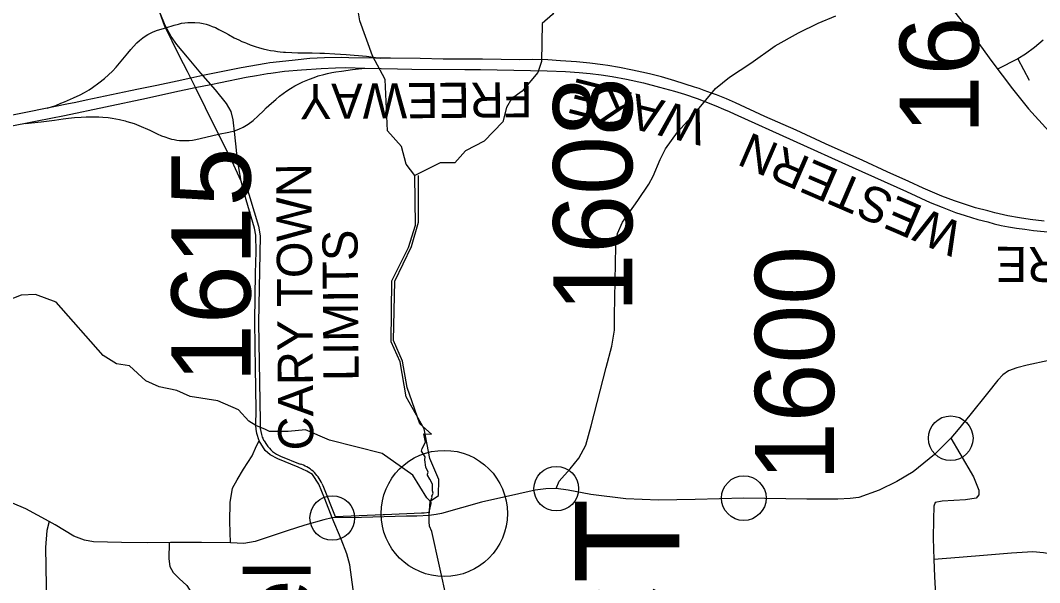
# Model space of a CAD drawing. Extents: x 2026893 to 2039781, y 729195 to 739590.
# Drawn here: x 2027257 to 2027941, y 735368 to 735746 of the extents above; entities that cross this region are included whole.
import ezdxf

# ---------------------------------------------------------------- set-up
doc = ezdxf.new("R2010")
doc.units = 0
doc.layers.add('Default', color=7, linetype='Continuous')
doc.layers.add('Old_Level_62', color=7, linetype='Continuous')

msp = doc.modelspace()

# ---------------------------------------------------------------- linework, layer by layer
at = {"layer": 'Default'}
for p, q in [((2027524.98, 735474.28), (2027516.61, 735498.7)), ((2027532.86, 735467.41), (2027524.98, 735474.28)), ((2027528.76, 735461.95), (2027527.62, 735467.5)), ((2027527.62, 735467.5), (2027532.86, 735467.41)), ((2027420.41, 735462.82), (2027422, 735460.32)), ((2027526.56, 735457.76), (2027528.76, 735461.95)), ((2027431.36, 735452.64), (2027444.56, 735447.3)), ((2027526.21, 735455.95), (2027526.56, 735457.76)), ((2027528.6, 735452.03), (2027526.21, 735455.95)), ((2027528.3, 735450.01), (2027528.6, 735452.03)), ((2027529.13, 735445.14), (2027528.3, 735450.01)), ((2027530.64, 735441.82), (2027529.13, 735445.14)), ((2027530.17, 735440.43), (2027530.64, 735441.82)), ((2027530.17, 735439.86), (2027530.17, 735440.43)), ((2027531.8, 735437.05), (2027530.17, 735439.86)), ((2027459.24, 735434.17), (2027459.85, 735432.79)), ((2027459.85, 735432.79), (2027468.11, 735412.09)), ((2027533.42, 735433.67), (2027531.8, 735437.05)), ((2027533.57, 735429.32), (2027533.42, 735433.67)), ((2027532.34, 735422.76), (2027533.28, 735425.07)), ((2027533.12, 735425.73), (2027533.99, 735427.6)), ((2027533.28, 735425.07), (2027533.12, 735425.73)), ((2027533.99, 735427.6), (2027533.57, 735429.32)), ((2027531.29, 735414.83), (2027532.53, 735420.69)), ((2027532.53, 735420.69), (2027532.34, 735422.76)), ((2027468.11, 735412.09), (2027500.45, 735413.32)), ((2027501.26, 735413.35), (2027526.17, 735414.47)), ((2027527.91, 735414.57), (2027531.29, 735414.83))]:
    msp.add_line(p, q, dxfattribs=at)
for points in [[(2027407.12, 735638.38), (2027416.67, 735607.09), (2027417.73, 735600.72), (2027416.67, 735542.12), (2027417.65, 735476.15)], [(2027516.61, 735498.7), (2027513.35, 735516.52), (2027507.26, 735530.38), (2027508.28, 735570.26), (2027519.44, 735593.58), (2027524.17, 735609.8), (2027524.17, 735641.23)]]:
    msp.add_lwpolyline(points, dxfattribs=at)
for centre, radius, start, end in [((2030089.05, 735530.09), 2671.94, 181.15687, 181.22222), ((2027441.76, 735473.6), 24.05, 181.20318, 200.27313), ((2027436.5, 735472.29), 18.67, 202.09732, 210.4951), ((2027439.63, 735472.25), 21.28, 214.09886, 247.1469), ((2027437.47, 735424.6), 23.78, 48.43914, 72.66828), ((2027437.47, 735424.6), 23.78, 23.72361, 48.4166), ((2027495.98, 735531.26), 118.03, 272.16812, 272.56587), ((2027523.57, 735472.53), 58.12, 272.56587, 274.28769)]:
    msp.add_arc(centre, radius, start, end, dxfattribs=at)
at = {"layer": 'Old_Level_62'}
for p, q in [((2027353.71, 735741.43), (2027350.15, 735751.52)), ((2027926.64, 735719.59), (2027913.12, 735712.74)), ((2027926.64, 735719.59), (2027934.3, 735705.36)), ((2027379.25, 735708.42), (2027371.14, 735706.64)), ((2027374.11, 735700.35), (2027384.55, 735702.46)), ((2027414.9, 735473.27), (2027414.9, 735473.27)), ((2027414.9, 735473.27), (2027414.9, 735473.27)), ((2027531.24, 735412.73), (2027531.24, 735412.73)), ((2027531.24, 735412.73), (2027531.24, 735412.73))]:
    msp.add_line(p, q, dxfattribs=at)
for points in [[(2027521.67, 735641.36), (2027515.72, 735648.85), (2027512.62, 735660.86), (2027503.18, 735671.36), (2027501.72, 735705.85), (2027493.19, 735721.81), (2027484.61, 735745.33), (2027482.69, 735757.33), (2027476.2, 735767.3), (2027477.64, 735779.83), (2027475.06, 735798.31), (2027471.59, 735801.79), (2027466.1, 735802.82), (2027461.06, 735806.78), (2027442.15, 735844.76), (2027431.63, 735859.75), (2027427.47, 735870.4)], [(2027625.65, 735787.88), (2027623.58, 735773.41), (2027618.1, 735755.89), (2027614.04, 735749.42), (2027607.22, 735743.42), (2027606.7, 735717.91), (2027604.18, 735710.42), (2027593.69, 735697.88), (2027586.7, 735692.9), (2027583.23, 735686.89), (2027580.67, 735677.42), (2027568.2, 735664.39), (2027555.66, 735657.86), (2027548.61, 735649.87), (2027538.77, 735649.87), (2027521.67, 735641.36)], [(2027869.52, 735781.98), (2027871.69, 735772.47), (2027872.9, 735768.1), (2027876.18, 735762.11), (2027884.25, 735751.35), (2027895.8, 735736.41), (2027909.27, 735717.87), (2027923.14, 735699.41), (2027933.81, 735686.04), (2027947.48, 735671.05), (2027962.36, 735656.86), (2027977.92, 735642.45), (2027988.16, 735632.6), (2027991.44, 735627.77), (2027993.37, 735621.31), (2027994.44, 735615.03), (2027994.73, 735610.2), (2027994.34, 735605.47), (2027993.23, 735595.53), (2027990.33, 735576.05), (2027985.79, 735545.25), (2027983.71, 735530.05)], [(2027414.9, 735473.27), (2027415.08, 735483.62), (2027414.54, 735512.2), (2027414.35, 735526.1), (2027414.06, 735543.5), (2027414.64, 735575.65), (2027415.12, 735590.04), (2027414.93, 735601.17), (2027413.92, 735605.94), (2027408.26, 735624.96), (2027404.88, 735637.51), (2027403.43, 735646.49), (2027402.36, 735653.66), (2027401.82, 735658.24), (2027400.83, 735668.87), (2027399.67, 735678.76), (2027398.22, 735684.36), (2027395.03, 735689.67), (2027387.78, 735698.75), (2027377.83, 735709.95), (2027369.04, 735720.88), (2027361.79, 735729.23), (2027357.93, 735734.73), (2027353.97, 735742.17), (2027350.59, 735750.47)], [(2027616.66, 735430.74), (2027618.69, 735435.76), (2027626.03, 735444.07), (2027631.73, 735451.21), (2027636.46, 735459.9), (2027640.13, 735473.03), (2027650.28, 735512.18), (2027654.05, 735526.47), (2027655.69, 735537.28), (2027655.69, 735547.13), (2027656.36, 735582.08), (2027656.75, 735593.85), (2027657.72, 735602.35), (2027661.19, 735609.88), (2027671.44, 735624.56), (2027678.88, 735635.42), (2027681.87, 735640.82), (2027686.41, 735652.12), (2027689.99, 735659.17), (2027698.1, 735670.46), (2027711.48, 735685.11), (2027723.7, 735699.84), (2027733.08, 735707.27), (2027747.37, 735716.71), (2027763.75, 735728.39), (2027779.35, 735737.2), (2027792.59, 735743.57), (2027804.38, 735748.5)], [(2027274.58, 735686.5), (2027280.56, 735688.4), (2027283.95, 735689.79), (2027286.26, 735690.82), (2027292.27, 735693.4), (2027296.74, 735695.51), (2027299.7, 735697.09), (2027302.79, 735698.87), (2027305.1, 735700.38), (2027309.4, 735703.51), (2027313.11, 735706.39), (2027318.6, 735711.44), (2027320.98, 735714.05), (2027328.86, 735723.5), (2027330.76, 735725.89), (2027332.59, 735728.06), (2027334.9, 735730.43), (2027336.68, 735732.1), (2027338.83, 735733.82), (2027340.6, 735735), (2027342.38, 735736.13), (2027344.04, 735736.94), (2027345.87, 735737.8), (2027348.67, 735738.93), (2027354.31, 735740.42)], [(2027371.14, 735706.68), (2027368.94, 735711.12), (2027363.67, 735721.53), (2027358.66, 735731.56), (2027353.71, 735741.43)], [(2027354.31, 735740.42), (2027360.08, 735742.24), (2027362.88, 735743.07), (2027365.01, 735743.59), (2027367.24, 735743.85), (2027369.27, 735744.11), (2027371.5, 735744.22), (2027373.89, 735744.11), (2027377.22, 735743.8), (2027379.5, 735743.38), (2027381.56, 735742.94), (2027383.55, 735742.31), (2027385.51, 735741.53), (2027387.76, 735740.64), (2027389.96, 735739.51), (2027394.48, 735737.14), (2027396.44, 735736.04), (2027400.39, 735733.9), (2027403.33, 735732.49), (2027405.47, 735731.45), (2027407.35, 735730.61), (2027408.56, 735730.12), (2027411.14, 735729.14), (2027412.96, 735728.47), (2027414.38, 735728.01), (2027417.24, 735727.11), (2027419.77, 735726.47), (2027422.63, 735725.74), (2027424.67, 735725.39), (2027427.07, 735724.98), (2027429.4, 735724.66), (2027431.23, 735724.46), (2027433.52, 735724.24), (2027434.72, 735724.14), (2027438.97, 735723.97), (2027443.04, 735723.74), (2027447.8, 735723.79), (2027452.71, 735723.65), (2027457.86, 735723.56), (2027461.01, 735723.42), (2027467.83, 735723.14), (2027475.6, 735722.59), (2027489.26, 735721.43), (2027498.46, 735720.15)], [(2027943.65, 735732.13), (2027937.91, 735727.24), (2027931.96, 735722.78), (2027926.64, 735719.59)], [(2027472.07, 735720.63), (2027461.01, 735720.27), (2027451.13, 735719.8), (2027441.25, 735718.85), (2027430.67, 735717.69), (2027424.35, 735716.93), (2027421.72, 735716.54), (2027405.06, 735713.68), (2027391.51, 735710.87), (2027379.25, 735708.42)], [(2027498.46, 735720.15), (2027495.15, 735720.13), (2027477.33, 735720.46), (2027472.07, 735720.63)], [(2027721.05, 735696.64), (2027716.11, 735698.42), (2027712.61, 735699.69), (2027709.48, 735700.74), (2027696.39, 735704.95), (2027687.45, 735707.5), (2027680.21, 735709.28), (2027677.37, 735710.06), (2027667.85, 735712.12), (2027659.04, 735713.83), (2027651.3, 735715.16), (2027648.01, 735715.61), (2027639.23, 735716.71), (2027630.35, 735717.64), (2027619.4, 735718.44), (2027610.98, 735718.91), (2027600.6, 735719.25), (2027592.3, 735719.02), (2027567.03, 735719.41), (2027540.78, 735719.55), (2027525.29, 735719.84), (2027505.2, 735720.18), (2027498.46, 735720.15)], [(2027384.55, 735702.46), (2027391.2, 735703.85), (2027408.37, 735707.41), (2027415.39, 735708.54), (2027422.66, 735709.75), (2027424.83, 735710.1), (2027434.2, 735711.29), (2027445.46, 735712.21), (2027458.67, 735713.13), (2027468.43, 735713.59), (2027475.19, 735713.82), (2027488.02, 735713.43)], [(2027400.57, 735671.34), (2027403.33, 735672.4), (2027406.31, 735673.82), (2027409.64, 735675.74), (2027412.97, 735678.29), (2027416.31, 735681.27), (2027419.99, 735684.74), (2027421.83, 735686.66), (2027425.34, 735689.89), (2027428.18, 735692.36), (2027430.71, 735694.52), (2027433.18, 735696.38), (2027435.71, 735698.17), (2027438.12, 735699.65), (2027441.09, 735701.45), (2027443.8, 735702.81), (2027446.49, 735704.17), (2027450.95, 735706.05), (2027454.06, 735707.22), (2027456.77, 735708.19), (2027460.46, 735709.16), (2027463.01, 735709.89), (2027465.9, 735710.46), (2027468.57, 735710.88), (2027472.45, 735711.36), (2027479.7, 735712.46), (2027488.02, 735713.43)], [(2027488.02, 735713.43), (2027509.94, 735712.92), (2027519.55, 735712.69), (2027555.31, 735712.46), (2027565.74, 735712.6), (2027610.59, 735711.65), (2027622.91, 735711.2), (2027631.99, 735710.53), (2027639.39, 735709.81), (2027646.9, 735708.84), (2027654.17, 735707.74), (2027663.87, 735706.05), (2027675.26, 735703.5), (2027686.11, 735700.71), (2027696.17, 735698.04), (2027702.71, 735695.98), (2027711.32, 735692.95), (2027716.42, 735690.99)], [(2027371.14, 735706.64), (2027362.01, 735704.72), (2027348.4, 735701.75), (2027336.06, 735699.27), (2027330.75, 735698.15), (2027317.8, 735695.41), (2027300.79, 735691.91), (2027293.99, 735690.38), (2027287.96, 735689.24), (2027280.2, 735687.65), (2027274.58, 735686.5)], [(2027374.3, 735700.51), (2027371.56, 735705.79), (2027371.14, 735706.68)], [(2027214.44, 735667), (2027246.5, 735673.75), (2027267.91, 735677.92), (2027286.27, 735681.62), (2027341.47, 735693.23), (2027360.32, 735697.44), (2027374.11, 735700.35)], [(2027389.8, 735669.14), (2027381.12, 735686.67), (2027374.3, 735700.51)], [(2027944.5, 735610.65), (2027935.04, 735611.58), (2027927.91, 735612.76), (2027920.03, 735614.19), (2027911.31, 735616.2), (2027906.62, 735617.46), (2027898.39, 735619.46), (2027891.47, 735621.72), (2027884.08, 735624.23), (2027875.61, 735627.45), (2027863.09, 735632.82), (2027853.54, 735637.24), (2027838.88, 735643.82), (2027822.51, 735651.38), (2027797.46, 735662.63), (2027777.8, 735671.76), (2027756.71, 735680.91), (2027736.98, 735690.08), (2027731.05, 735692.79), (2027724.21, 735695.51), (2027721.05, 735696.64)], [(2027274.58, 735686.5), (2027244.99, 735680.54), (2027225.25, 735676.19), (2027214.44, 735673.87)], [(2027716.42, 735690.99), (2027723.85, 735688.18), (2027729.05, 735685.94), (2027732.8, 735684.35), (2027736.19, 735682.76), (2027815.43, 735646.96), (2027851.95, 735630.57), (2027867.83, 735623.16), (2027875.98, 735619.98), (2027884.75, 735616.47), (2027891.38, 735614.32), (2027899.95, 735611.79), (2027906.57, 735610.01), (2027910.73, 735608.85), (2027915.46, 735607.68), (2027920.49, 735606.81), (2027925.91, 735605.94), (2027931.42, 735605.17), (2027937.32, 735604.3), (2027949.02, 735603.23)], [(2027259.99, 735676.25), (2027270.62, 735677.31), (2027279.6, 735678.49), (2027285.49, 735679.26), (2027289.06, 735679.75), (2027293, 735680.28), (2027297.59, 735680.54), (2027300.82, 735680.73), (2027303.74, 735680.78), (2027307.73, 735680.78), (2027309.33, 735680.68), (2027312.04, 735680.54), (2027315.73, 735680.17), (2027318.34, 735679.8), (2027323.34, 735678.82), (2027326.99, 735678.01), (2027328.29, 735677.59), (2027333.1, 735676.11), (2027336.33, 735674.88), (2027343.63, 735671.67), (2027348.59, 735669.32), (2027351.58, 735668.01), (2027353.69, 735667.23), (2027356.12, 735666.36), (2027358.23, 735665.74), (2027359.95, 735665.35), (2027361.76, 735665.03), (2027363.54, 735664.84), (2027365.57, 735664.7), (2027367.96, 735664.7), (2027369.99, 735664.75), (2027372.26, 735665.04), (2027374.6, 735665.46), (2027377.41, 735666.02), (2027389.8, 735669.14)], [(2027389.8, 735669.14), (2027396.67, 735670.28), (2027400.57, 735671.34)], [(2027404.88, 735637.51), (2027398.64, 735651.14), (2027390.42, 735667.9), (2027389.8, 735669.14)], [(2027531.91, 735422.35), (2027537.64, 735426.16), (2027537.77, 735436.88), (2027531.75, 735450.92), (2027527.83, 735470.9), (2027515.87, 735492.38), (2027511.82, 735515.89), (2027505.8, 735529.34), (2027506.24, 735570.37), (2027517.33, 735592.87), (2027522.16, 735607.87), (2027521.67, 735641.36)], [(2027531.91, 735422.35), (2027529.76, 735424.46), (2027520.31, 735439.87), (2027499.74, 735454.4), (2027464.29, 735463.33), (2027448.29, 735470.36), (2027436.61, 735469.15), (2027424.08, 735469.24), (2027421.25, 735470.49), (2027414.9, 735473.27), (2027410.24, 735476.09), (2027403.28, 735483.79), (2027389.23, 735489.8), (2027370.79, 735492.8), (2027361.81, 735496.76), (2027349.85, 735499.27), (2027340.88, 735503.3), (2027329.86, 735513.26), (2027321.23, 735514.76), (2027312.29, 735520.27), (2027280.74, 735556.21), (2027266.86, 735561.19), (2027257.21, 735560.71), (2027246.88, 735556.69)], [(2027983.71, 735530.05), (2027977.17, 735525.38), (2027969.34, 735521.9), (2027959.58, 735519.3), (2027947.65, 735516.81), (2027933.02, 735513.67), (2027926.16, 735512.03), (2027920.41, 735509.88), (2027916.69, 735507.23), (2027913.21, 735503.56), (2027906.3, 735495.02), (2027894.52, 735480.25), (2027886.59, 735470.45), (2027881.62, 735464.65)], [(2027417.1, 735462.96), (2027415.41, 735467.89), (2027415.08, 735470.67), (2027414.9, 735473.27)], [(2027397.8, 735394.32), (2027397.27, 735408.59), (2027397.51, 735421.5), (2027399.06, 735430.96), (2027402.25, 735436.66), (2027406.6, 735443.9), (2027412.3, 735452.78), (2027415.19, 735459.44), (2027417.1, 735462.96)], [(2027466.18, 735411.02), (2027461.26, 735424.01), (2027457.2, 735433.66), (2027452.85, 735440.32), (2027448.99, 735442.54), (2027443.38, 735445.25), (2027429.66, 735450.77), (2027424.5, 735453.38), (2027421.02, 735456.47), (2027417.1, 735462.96)], [(2027881.62, 735464.65), (2027870.85, 735453.7), (2027856.45, 735442.11), (2027845.34, 735435.57), (2027833.6, 735429.78), (2027819.88, 735424.85), (2027814.13, 735424.1), (2027805.87, 735423.77), (2027784.96, 735423.67), (2027742.64, 735424.35), (2027710.08, 735423.43), (2027685.35, 735423.04), (2027663.32, 735423.82), (2027639.84, 735426.76), (2027624.58, 735429.7), (2027616.66, 735430.74)], [(2027881.62, 735464.65), (2027887.75, 735454.4), (2027896.93, 735438.66), (2027900.6, 735429.68), (2027900.51, 735426.69), (2027898.67, 735424.27), (2027891.62, 735423.21), (2027875.87, 735422.25), (2027871.18, 735421.4), (2027870.22, 735419.04), (2027870.07, 735410.11), (2027869.88, 735397.46), (2027870.31, 735383.17)], [(2027275.97, 735408.73), (2027260.23, 735417.23), (2027251.43, 735421.09), (2027238.15, 735426.18), (2027227.91, 735428.93), (2027214.96, 735431.35), (2027214.44, 735431.44)], [(2027616.66, 735430.74), (2027609.6, 735430.6), (2027602.45, 735429.63), (2027591.44, 735427.22), (2027566.42, 735421.62), (2027539.66, 735414.12), (2027535.99, 735413.41), (2027531.24, 735412.73)], [(2027560.87, 735266.42), (2027563.01, 735274.94), (2027562.35, 735281.42), (2027556.94, 735285.92), (2027554.46, 735299.9), (2027556.98, 735307.39), (2027555.37, 735334.94), (2027549.38, 735349.94), (2027543.39, 735355.4), (2027532.99, 735401.95), (2027531.51, 735405.58), (2027531.2, 735408.53), (2027531.24, 735412.73), (2027531.91, 735422.35)], [(2027531.24, 735412.73), (2027522.91, 735412.2), (2027515.99, 735412.21), (2027485.75, 735411.24), (2027466.18, 735411.02)], [(2028025.55, 735412.72), (2028022.58, 735405.38), (2028018.42, 735398.81), (2028012.91, 735393.69), (2028005.38, 735389.54), (2027995.81, 735386.16), (2027985.57, 735383.99), (2027977.46, 735383.22), (2027963.84, 735384.47), (2027944.08, 735387.59), (2027936.74, 735388.26), (2027922.39, 735387.47), (2027906.25, 735385.92), (2027887.37, 735384.55), (2027870.31, 735383.17)], [(2027275.97, 735408.73), (2027274.34, 735402.62), (2027273.56, 735391.11), (2027274.33, 735339.56), (2027272.98, 735316.39), (2027270.47, 735272.55), (2027269.65, 735257.06), (2027269.25, 735253.92), (2027268.12, 735250.96)], [(2027397.8, 735394.32), (2027378.43, 735394.49), (2027357.52, 735394.56), (2027342.25, 735394.42), (2027324.62, 735394.49), (2027305.78, 735395.07), (2027299.84, 735396.21), (2027292.54, 735398.76), (2027280.08, 735406.37), (2027275.97, 735408.73)], [(2027466.18, 735411.02), (2027460.51, 735409.72), (2027447.85, 735406.15), (2027435.97, 735402.38), (2027414.42, 735395.19), (2027406.69, 735393.94), (2027397.8, 735394.32)], [(2027547.19, 735118.61), (2027539.13, 735138.77), (2027532.12, 735154.89), (2027524.34, 735174.2), (2027518.16, 735191.29), (2027511.45, 735213.27), (2027503.67, 735241.18), (2027500.58, 735255.27), (2027495.94, 735277.4), (2027489.71, 735304.2), (2027486.23, 735321.38), (2027483.86, 735337.09), (2027480.19, 735362.92), (2027477.97, 735379.52), (2027475.89, 735386.93), (2027472.22, 735396.88), (2027466.18, 735411.02)], [(2027356.52, 735394.55), (2027356.4, 735383.55), (2027357.08, 735378.42), (2027359.2, 735374.34), (2027363.23, 735370.31), (2027368.55, 735365.63), (2027371.66, 735360.64), (2027372.6, 735356.89), (2027373.14, 735344.88), (2027372.15, 735299.55), (2027372.15, 735299.11)], [(2027870.31, 735383.17), (2027870.7, 735371.68), (2027871.76, 735351.12), (2027872.83, 735328.74)]]:
    msp.add_lwpolyline(points, dxfattribs=at)
for centre, radius in [((2027881.62, 735464.65), 15), ((2027541.43, 735414.07), 42.42), ((2027616.66, 735430.74), 15), ((2027742.64, 735424.35), 15), ((2027466.18, 735411.02), 15)]:
    msp.add_circle(centre, radius, dxfattribs=at)

# ---------------------------------------------------------------- texts
at = {"layer": 'Default'}
for s, p in [('CARY TOWN', (2027453.56, 735456.54)), ('LIMITS', (2027483.94, 735503.13))]:
    msp.add_text(s, height=23.622, rotation=90.45816, dxfattribs=at).set_placement(p)
at = {"layer": 'Old_Level_62'}
for s, height, rotation, p in [('1601', 53.149, 90, (2027900.49, 735668.95)), ('WAKE', 23.622, 165.89835, (2027719.29, 735684.08)), ('FREEWAY', 23.622, 180.48751, (2027600.58, 735704.05)), ('1608', 53.15, 90, (2027667.74, 735549.19)), ('WESTERN', 23.622, 156.62941, (2027891.64, 735608.05)), ('1615', 53.15, 90, (2027411.3, 735501.87)), ('1600', 53.15, 90, (2027803.28, 735435.81)), ('FUTURE', 23.622, 179.63197, (2028040.16, 735592.53)), ('PROJECT', 70, 90, (2027699.31, 734987.36)), ('Green Level', 43.307, 90, (2027451.67, 735066.75))]:
    msp.add_text(s, height=height, rotation=rotation, dxfattribs=at).set_placement(p)

doc.saveas('drawing.dxf')
